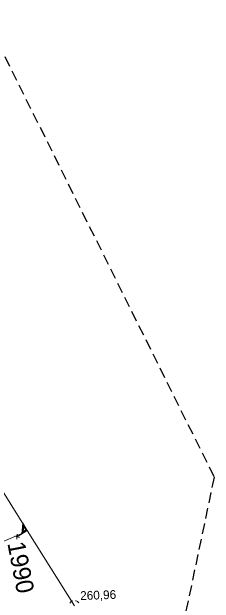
# Model space of a CAD drawing. Extents: x -732074 to -731966, y -1048695 to -1047982.
# Drawn here: x -732004.9 to -731986.5, y -1048122.1 to -1048068.3 of the extents above; entities that cross this region are included whole.
import ezdxf

# ---------------------------------------------------------------- set-up
doc = ezdxf.new("R2010")
doc.units = 0
doc.header["$LTSCALE"] = 0.32
doc.linetypes.add('MEDIUM_DASHED', pattern=[4.5, 3, -1.5])
doc.layers.add('1', color=7, linetype='Continuous')
for name, color, linetype, lineweight in [('18', 7, 'Continuous', 13), ('20', 7, 'Continuous', 13), ('49', 7, 'Continuous', 13), ('63', 7, 'MEDIUM_DASHED', 25)]:
    doc.layers.add(name, color=color, linetype=linetype, lineweight=lineweight)

msp = doc.modelspace()

# ---------------------------------------------------------------- linework, layer by layer
at = {"layer": '18'}
for p, q in [((-732004.664, -1048116.023), (-732004.258, -1048116.165)), ((-732004.473, -1048116.304), (-732004.463, -1048115.86))]:
    msp.add_line(p, q, dxfattribs=at)
for points in [[(-732004.469, -1048116.091), (-732003.54, -1048115.511), (-732003.948, -1048114.857), (-732004.03, -1048115.817)], [(-732003.957, -1048115.711), (-732003.604, -1048115.491), (-732003.904, -1048115.012), (-732003.958, -1048115.712)], [(-732003.911, -1048115.627), (-732003.664, -1048115.473), (-732003.86, -1048115.158), (-732003.91, -1048115.629)], [(-731999.392, -1048121.927), (-731999.463, -1048121.955), (-731999.529, -1048121.994), (-731999.59, -1048122.042), (-731999.641, -1048122.099), (-731999.664, -1048122.133)], [(-731998.85, -1048122.11), (-731998.901, -1048122.052), (-731998.958, -1048122.002), (-731999.024, -1048121.961), (-731999.095, -1048121.932), (-731999.144, -1048121.918)]]:
    msp.add_lwpolyline(points, dxfattribs=at)
at = {"layer": '20'}
msp.add_lwpolyline([(-731999.239, -1048122.39), (-732003.535, -1048115.515), (-732011.701, -1048102.444), (-732015.041, -1048097.097), (-732020.556, -1048088.271), (-732022.199, -1048085.64)], dxfattribs=at)
msp.add_lwpolyline([(-731999.239, -1048122.39), (-732003.535, -1048115.515), (-732011.701, -1048102.444), (-732015.041, -1048097.097), (-732020.556, -1048088.271), (-732022.199, -1048085.64)], dxfattribs=at)
at = {"layer": '49'}
msp.add_lwpolyline([(-732009.44, -1048118.09), (-732004.02, -1048115.8), (-732003.535, -1048115.515)], dxfattribs=at)
msp.add_lwpolyline([(-732009.44, -1048118.09), (-732004.02, -1048115.8), (-732003.535, -1048115.515)], dxfattribs=at)
at = {"layer": '63'}
msp.add_lwpolyline([(-732014.559, -1048054.287), (-731986.534, -1048110.653), (-731986.533, -1048110.655), (-731986.533, -1048110.657), (-731986.533, -1048110.659), (-732043.346, -1048381.295)], dxfattribs=at)

# ---------------------------------------------------------------- texts
at = {"layer": '1'}
for s, height, rotation, p in [('1990', 1.6, 281, (-732005.355, -1048116.685)), ('260,96', 0.8, 2, (-731998.709, -1048121.858))]:
    msp.add_text(s, height=height, rotation=rotation, dxfattribs=at).set_placement(p)

doc.saveas('drawing.dxf')
